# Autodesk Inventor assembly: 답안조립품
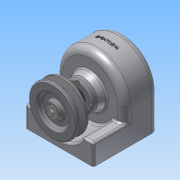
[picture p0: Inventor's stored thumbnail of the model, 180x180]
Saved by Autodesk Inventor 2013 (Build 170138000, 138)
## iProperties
Created: 2015-02
Part Number: 답안조립품
Document SubType Name: Assembly
Designer: Administrator
Author: Administrator
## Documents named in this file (14)
- C:\Documents and Settings\Administrator\바탕 화면\450214V1022\답안조립품.iam
- C:\Documents and Settings\Administrator\바탕 화면\450214V1022\1-본체.ipt
- C:\Documents and Settings\Administrator\바탕 화면\450214V1022\베어링 6001.ipt
- C:\Documents and Settings\Administrator\바탕 화면\450214V1022\축.ipt
- C:\Documents and Settings\Administrator\바탕 화면\450214V1022\5-스퍼기어.ipt
- C:\Documents and Settings\Administrator\바탕 화면\450214V1022\키5x5.ipt
- C:\Documents and Settings\Administrator\바탕 화면\450214V1022\오일실.ipt
- C:\Documents and Settings\Administrator\바탕 화면\450214V1022\축커버.ipt
- C:\Documents and Settings\Administrator\바탕 화면\450214V1022\M3x0.5.ipt
- C:\Documents and Settings\Administrator\바탕 화면\450214V1022\4-V-벨트풀리.ipt
- C:\Documents and Settings\Administrator\바탕 화면\450214V1022\와샤.ipt
- C:\Documents and Settings\Administrator\바탕 화면\450214V1022\키4x4.ipt
- C:\Documents and Settings\Administrator\바탕 화면\450214V1022\M5x0.8.ipt
- M5x0.8.ipt
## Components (7 placed, 4 different names)
1. 1-본체:1
2. 4-V-벨트풀리:1 — 각도:4
3. M5x0.8:1 — 각도:20
4. M3x0.5:1
5. M3x0.5:2
6. M3x0.5:3
7. M3x0.5:4
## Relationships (2: Angle 2)
- 각도:4 [Angle]: 4-V-벨트풀리:1
- 각도:20 [Angle]: M5x0.8:1
